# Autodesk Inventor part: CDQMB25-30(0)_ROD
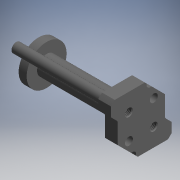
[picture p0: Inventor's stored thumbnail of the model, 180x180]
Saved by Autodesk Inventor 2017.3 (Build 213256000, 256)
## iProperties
Part Number: CDQMB25-30(0)_ROD
Material: Generic
Catalog Web Link: www.cadenas.de
Description: CQM_ROD-Compact Cylinder Guide Rod Type
Vendor: SMC
Document SubType Name: Modeling
Designer: partserver
Manufacturer: SMC
Mass: 19.2101 g
Surface Area: 86.46 cm^2
Volume: 19.2101 cm^3
Density: 1 g/cm^3
Appearance: PSOLRGB-128-128-128
Category: PARTsolutions
Company: SMC
Title: CDQMB25-30_ROD
Author: Cadenas PARTsolutions
Comments: Compact Cylinder Guide Rod Type
PSOL_IDENT_0: {$CADENAS_DATA\23d-libs\smc_jp\actuator\compact_cylinder\cqm\parts\cqm_rod.prj},207 {VTYP=3D},{NB=CD
PSOL_IDENT_1: QMB25-30(0)_ROD},{LINA=CDQMB25-30_ROD},{NN=CQM_ROD},{DATE=09.12.2020 02:52:29},{GEOMDATE=26.03.2020
PSOL_IDENT_2: 06:55:43},{VERSION=},{LINEID=40},{WBVAR=MAGNET,THREAD1,STROKE,THREAD2},{WBNUMERIC=STROKE}  {NB=CDQMB
PSOL_IDENT_3: 25-30(0)_ROD},{LINA=CDQMB25-30_ROD},{KT=DUMMY},{BORE=25},{MAGNET=D},{MOUNT=(B) Through-hole/Both end
PSOL_IDENT_4: s tapped (Standard)},{MOUNTX=B},{THREAD1=},{THREAD1X='','(-) M thread'},{STROKE=30},{STROKEX=[1:50/1
PSOL_IDENT_5: ]},{STROKEX2=30},{SMAX=50},{THREAD2=0},{ORDER=CDQMB25-30},{B=32.5},{B1=22.5},{B2=32.5},{EB=38},{EC=0
PSOL_IDENT_6: .0},{HA=M5x0.8},{HARA=5},{HARP=0.80},{HB=5 +0.2/0},{HBX=5},{IB=50.5},{KA=22 +0.1/-0.1},{KAX=22},{KB=
PSOL_IDENT_7: 15.6},{L=5.0},{M=28.0},{N=5.4},{OB=9.0},{Q=11.0},{Q1=11.0},{RA=10},{RB=7.0},{T=1.0},{V=30.0},{W=8},{
PSOL_IDENT_8: Z=0},{PP=M5x0.8},{PTN=-},{PTF=-},{P=M5x0.8},{LC1=6},{LC2=2.00},{LC3=2.25},{LC4=8.27},{LC5=13.5},{LC6=
PSOL_IDENT_9: 12}
NB: CDQMB25-30(0)_ROD
NN: CQM_ROD
NT: Compact Cylinder Guide Rod Type
NBSYN: $ORDER.($THREAD2.)_ROD
LINA: CDQMB25-30_ROD
CATALOG: SMC (JP
BORE: 25
MAGNET: (D) With magnet
MOUNT: (B) Through-hole/Both ends tapped (Standard)
THREAD1: (-) M thread
STROKE: 30
SMAX: 50
THREAD2: on
B: 32.5
B1: 22.5
B2: 32.5
EB: 38
EC: 0
HA: M5x0.8
HARA: 5
HARP: 0.8
HB: 5 +0.2/0
HBX: 5
IB: 50.5
KA: 22 +0.1/-0.1
KAX: 22
KB: 15.6
L: 5
M: 28
N: 5.4
OB: 9
Q: 11
Q1: 11
RA: 10
RB: 7
T: 1
V: 30
W: 8
Z: 0
PP: M5x0.8
PTN: -
PTF: -
P: M5x0.8
LC1: 6
LC2: 2
LC3: 2.25
LC4: 8.27
LC5: 13.5
LC6: 12
SUPPLIER: SMC
ARTICLENO: CDQMB25-30(0)_ROD
BOMINFO: CDQMB25-30_ROD
CREATOR: CADENAS GmbH
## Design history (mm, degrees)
sketch "Sketch_11"
  geometry: L1 (-19, 16.63)-(-19, -2.213); L2 (-19, -2.213)-(-17.812, -3.402); L3 (-14.902, -6.312)-(-6.463, -14.75); L4 (-6.463, -14.75)-(5.548, -14.75); L5 (7.139, -15.409)-(10.73, -19); L6 (10.73, -19)-(16.63, -19); L7 (19, -16.63)-(19, 2.213); L8 (19, 2.213)-(17.812, 3.402); L9 (14.902, 6.312)-(6.463, 14.75); L10 (6.463, 14.75)-(-5.548, 14.75); L11 (-7.139, 15.409)-(-10.73, 19); L12 (-10.73, 19)-(-16.63, 19); C1 r 2.5 at (7.778, 7.778); C2 r 2.5 at (-7.778, -7.778); A1 r 2.25 centre (-17, -5.5) between (-14.902, -6.312) and (-17.812, -3.402); A2 r 2.25 centre (5.548, -17) between (7.139, -15.409) and (5.548, -14.75); A3 r 25.25 centre (0, 0) between (16.63, -19) and (19, -16.63); A4 r 2.25 centre (17, 5.5) between (14.902, 6.312) and (17.812, 3.402); A5 r 2.25 centre (-5.548, 17) between (-7.139, 15.409) and (-5.548, 14.75); A6 r 25.25 centre (0, 0) between (-16.63, 19) and (-19, 16.63); 2 further points
  constraints: 24 end point, 12 point on circle, 8 centre point
extrude "Extrusion1" join sketch "Sketch_11" distance "d0" = 8; taper "d1" = 0 deg
sketch "Sketch_12"
  geometry: L1 (-5, 11)-(-13, 11); L2 (-13, 11)-(-13, 13.5); L3 (-13, 13.5)-(-12.567, 13.067); L4 (-12.567, 13.067)-(-5.433, 13.067); L5 (-5.433, 13.067)-(-5, 13.5); L6 (-5, 13.5)-(-5, 11); L7 (-5, 11)-(-13, 11)
  constraints: 14 end point
revolve "Revolution1" sketch "Sketch_12" stored, may be unused: angle "d2" = 360 deg
thread "Thread1" dims "d3" = 7.134, "d4" = 0
sketch "Sketch_13"
  geometry: L1 (-5, -11)-(-13, -11); L2 (-13, -11)-(-13, -8.5); L3 (-13, -8.5)-(-12.567, -8.933); L4 (-12.567, -8.933)-(-5.433, -8.933); L5 (-5.433, -8.933)-(-5, -8.5); L6 (-5, -8.5)-(-5, -11); L7 (-5, -11)-(-13, -11)
  constraints: 14 end point
revolve "Revolution2" sketch "Sketch_13" stored, may be unused: angle "d5" = 360 deg
thread "Thread2" dims "d6" = 7.134, "d7" = 0
sketch "Sketch_2"
  geometry: L1 (51.25, 0)-(-5, 0); L2 (-5, 0)-(-5, 6); L3 (-5, 6)-(46.25, 6); L4 (46.25, 6)-(46.25, 12.5); L5 (46.25, 12.5)-(51.25, 12.5); L6 (51.25, 12.5)-(51.25, 0); L7 (51.25, 0)-(-5, 0)
  constraints: 14 end point
revolve "Revolution3" sketch "Sketch_2" stored, may be unused: angle "d8" = 360 deg
sketch "Sketch_3"
  geometry: L1 (51.25, 14)-(-5, 14); L2 (-5, 14)-(-5, 17); L3 (-5, 17)-(51.25, 17); L4 (51.25, 17)-(51.25, 14); L5 (51.25, 14)-(-5, 14)
  constraints: 10 end point
revolve "Revolution4" sketch "Sketch_3" stored, may be unused: angle "d9" = 360 deg
sketch "Sketch_4"
  geometry: L1 (51.25, -14)-(-5, -14); L2 (-5, -14)-(-5, -11); L3 (-5, -11)-(51.25, -11); L4 (51.25, -11)-(51.25, -14); L5 (51.25, -14)-(-5, -14)
  constraints: 10 end point
revolve "Revolution5" sketch "Sketch_4" stored, may be unused: angle "d10" = 360 deg
node "EB2_1_XY"
node "EB2_1_YZ"
node "EB2_1_ZX"
node "EB2_1_X"
node "EB2_1_Y"
node "EB2_1_Z"
node "EB2_1_Center"
node "EB2_2_XY"
node "EB2_2_YZ"
node "EB2_2_ZX"
node "EB2_2_X"
node "EB2_2_Y"
node "EB2_2_Z"
node "EB2_2_Center"
node "HB_XY"
node "HB_YZ"
node "HB_ZX"
node "HB_X"
node "HB_Y"
node "HB_Z"
node "HB_Center"
node "ROD_BODY_XY"
node "ROD_BODY_YZ"
node "ROD_BODY_ZX"
node "ROD_BODY_X"
node "ROD_BODY_Y"
node "ROD_BODY_Z"
node "ROD_BODY_Center"
node "W_XY"
node "W_YZ"
node "W_ZX"
node "W_X"
node "W_Y"
node "W_Z"
node "W_Center"
body "Solid1"
other parameters: "d11" = 0, "d12" = 0, "d13" = 0
